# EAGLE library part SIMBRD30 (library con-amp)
AMP connector
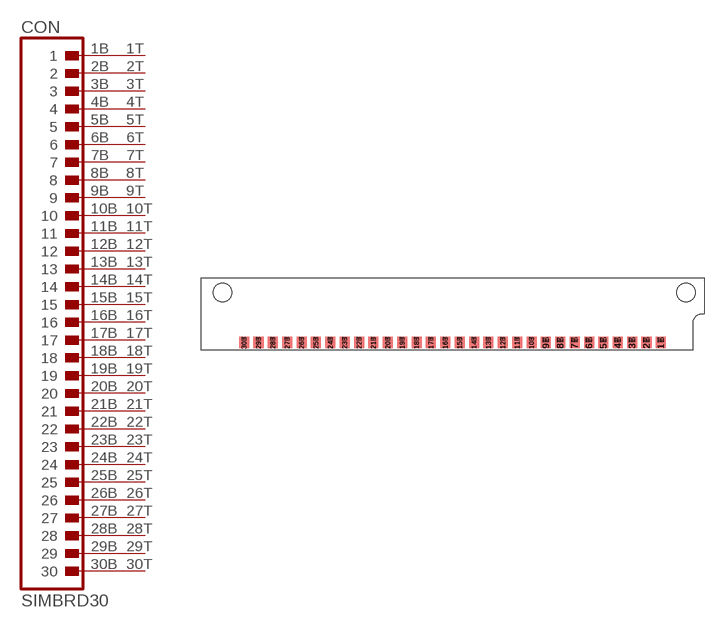
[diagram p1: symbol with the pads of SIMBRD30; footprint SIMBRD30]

Designator prefix CON

## SIMBRD30 (OC_FARNELL: unknown; OC_NEWARK: unknown)  [SIMBRD30]
1B  1  pas
1T  A1  pas
2B  2  pas
2T  A2  pas
3B  3  pas
3T  A3  pas
4B  4  pas
4T  A4  pas
5B  5  pas
5T  A5  pas
6B  6  pas
6T  A6  pas
7B  7  pas
7T  A7  pas
8B  8  pas
8T  A8  pas
9B  9  pas
9T  A9  pas
10B  10  pas
10T  A10  pas
11B  11  pas
11T  A11  pas
12B  12  pas
12T  A12  pas
13B  13  pas
13T  A13  pas
14B  14  pas
14T  A14  pas
15B  15  pas
15T  A15  pas
16B  16  pas
16T  A16  pas
17B  17  pas
17T  A17  pas
18B  18  pas
18T  A18  pas
19B  19  pas
19T  A19  pas
20B  20  pas
20T  A20  pas
21B  21  pas
21T  A21  pas
22B  22  pas
22T  A22  pas
23B  23  pas
23T  A23  pas
24B  24  pas
24T  A24  pas
25B  25  pas
25T  A25  pas
26B  26  pas
26T  A26  pas
27B  27  pas
27T  A27  pas
28B  28  pas
28T  A28  pas
29B  29  pas
29T  A29  pas
30B  30  pas
30T  A30  pas

## Footprint SIMBRD30 (pad centres in mm)
SIMM Modul
smd 1.778 x 2.032 bottom: 1B 36.83,-6.35; 2B 34.29,-6.35; 3B 31.75,-6.35; 4B 29.21,-6.35; 5B 26.67,-6.35; 6B 24.13,-6.35; 7B 21.59,-6.35; 8B 19.05,-6.35; 9B 16.51,-6.35; 10B 13.97,-6.35; 11B 11.43,-6.35; 12B 8.89,-6.35; 13B 6.35,-6.35; 14B 3.81,-6.35; 15B 1.27,-6.35; 16B -1.27,-6.35; 17B -3.81,-6.35; 18B -6.35,-6.35; 19B -8.89,-6.35; 20B -11.43,-6.35; 21B -13.97,-6.35; 22B -16.51,-6.35; 23B -19.05,-6.35; 24B -21.59,-6.35; 25B -24.13,-6.35; 26B -26.67,-6.35; 27B -29.21,-6.35; 28B -31.75,-6.35; 29B -34.29,-6.35; 30B -36.83,-6.35
smd 1.778 x 2.032: 1T 36.83,-6.35; 2T 34.29,-6.35; 3T 31.75,-6.35; 4T 29.21,-6.35; 5T 26.67,-6.35; 6T 24.13,-6.35; 7T 21.59,-6.35; 8T 19.05,-6.35; 9T 16.51,-6.35; 10T 13.97,-6.35; 11T 11.43,-6.35; 12T 8.89,-6.35; 13T 6.35,-6.35; 14T 3.81,-6.35; 15T 1.27,-6.35; 16T -1.27,-6.35; 17T -3.81,-6.35; 18T -6.35,-6.35; 19T -8.89,-6.35; 20T -11.43,-6.35; 21T -13.97,-6.35; 22T -16.51,-6.35; 23T -19.05,-6.35; 24T -21.59,-6.35; 25T -24.13,-6.35; 26T -26.67,-6.35; 27T -29.21,-6.35; 28T -31.75,-6.35; 29T -34.29,-6.35; 30T -36.83,-6.35
hole 3.302 at -40.64,2.54
hole 3.302 at 41.275,2.54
